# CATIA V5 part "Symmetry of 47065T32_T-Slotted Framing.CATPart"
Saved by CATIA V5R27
Part number: Symmetry of 47065T32_T-Slotted Framing
Bounding box of the stored display mesh (mm): x -38.1 to 38.1, y -44.45 to 44.45, z -3.175 to 3.175
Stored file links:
  \\triton.meca.polymtl.ca\usagers\zaoue\profiles\Desktop\varm_ass\structure prismatique\Symmetry of 47065T32_T-Slotted Framing.CATPart
  \\triton.meca.polymtl.ca\usagers\zaoue\profiles\Desktop\varm_ass\structure prismatique\30deg_bracket.CATPart
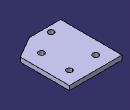
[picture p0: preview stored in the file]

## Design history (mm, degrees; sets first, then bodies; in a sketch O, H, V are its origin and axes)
Body1 (main body)
  Body2 "Corps du corps principal d'origine"
    Solid1: linked copy from another document
  Assemble1: tool Body2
